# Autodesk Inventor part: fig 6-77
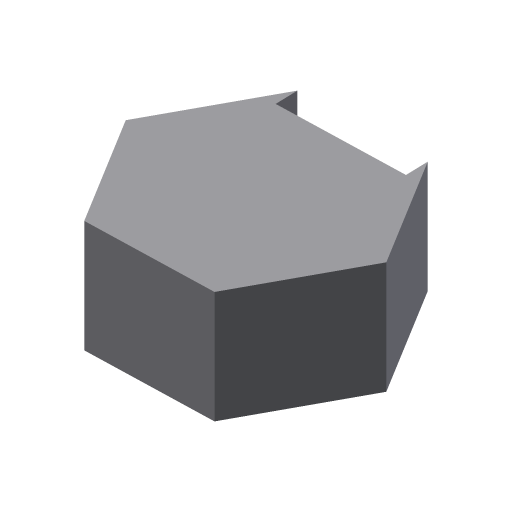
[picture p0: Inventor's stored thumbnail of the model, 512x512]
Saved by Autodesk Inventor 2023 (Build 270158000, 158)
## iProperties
Created: 2009-03
Part Number: fig 6-77
Document SubType Name: Modeling
Designer: Sham
Density: 1 g/cm^3
Material: Generic
Appearance: Default
Author: Sham
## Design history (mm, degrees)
sketch "Sketch5"
  geometry: L1 (-5.929, 9.627)-(5.372, 9.948); L2 (5.372, 9.948)-(11.301, 0.321); L3 (11.301, 0.321)-(5.929, -9.627); L4 (5.929, -9.627)-(-5.372, -9.948); L5 (-5.372, -9.948)-(-11.301, -0.321); L6 (-11.301, -0.321)-(-5.929, 9.627); 1 further point
  constraints: 12 end point, 13 other
extrude "Extrusion3" new body sketch "Sketch5" distance "d13" = 10; taper "d14" = 0 deg
thicken "Thicken2" dims "d15" = 2, "d16" = 2
body "Solid4"
